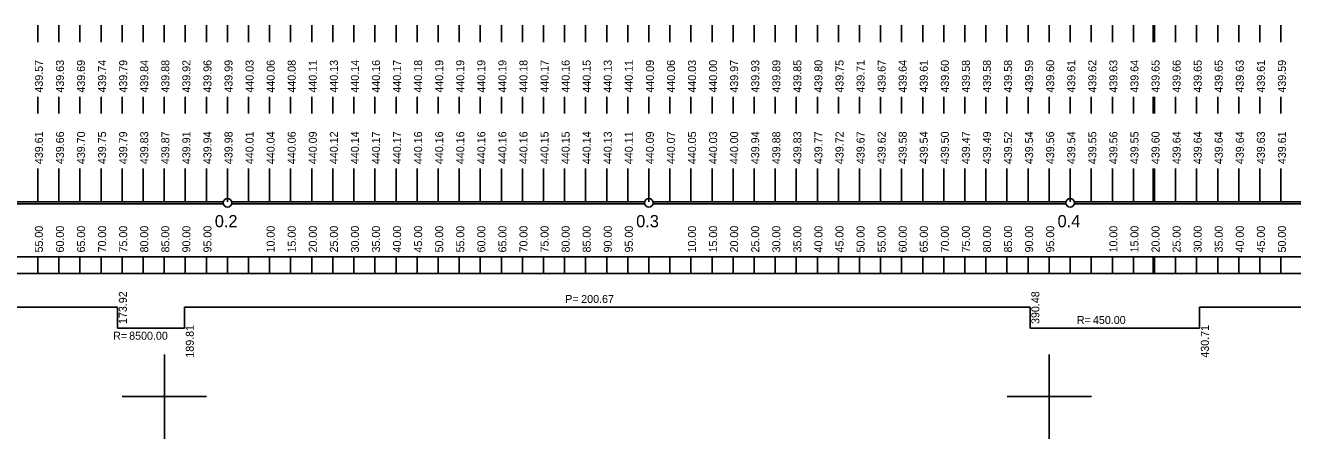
# Model space of a CAD drawing. Extents: x -240 to 1040, y 276 to 593.
# Drawn here: x 157 to 457.8, y 275.7 to 374 of the extents above; entities that cross this region are included whole.
import ezdxf

# ---------------------------------------------------------------- set-up
doc = ezdxf.new("R2010")
doc.units = 0
for name, color, linetype in [('1', 7, 'Continuous'), ('2', 7, 'Continuous'), ('FORMATY', 7, 'Continuous')]:
    doc.layers.add(name, color=color, linetype=linetype)

msp = doc.modelspace()

# ---------------------------------------------------------------- linework, layer by layer
at = {"layer": '1'}
for p, q in [((160, 374), (160, 370)), ((165, 370), (165, 374)), ((170, 374), (170, 370)), ((175, 370), (175, 374)), ((180, 374), (180, 370)), ((185, 370), (185, 374)), ((190, 374), (190, 370)), ((195, 370), (195, 374)), ((200, 374), (200, 370)), ((205, 370), (205, 374)), ((210, 374), (210, 370)), ((215, 370), (215, 374)), ((220, 374), (220, 370)), ((225, 370), (225, 374)), ((230, 374), (230, 370)), ((235, 370), (235, 374)), ((240, 374), (240, 370)), ((245, 370), (245, 374)), ((250, 374), (250, 370)), ((255, 370), (255, 374)), ((260, 374), (260, 370)), ((265, 370), (265, 374)), ((270, 374), (270, 370)), ((275, 370), (275, 374)), ((280, 374), (280, 370)), ((285, 370), (285, 374)), ((290, 374), (290, 370)), ((295, 370), (295, 374)), ((300, 374), (300, 370)), ((305, 370), (305, 374)), ((310, 374), (310, 370)), ((315, 370), (315, 374)), ((320, 374), (320, 370)), ((325, 370), (325, 374)), ((330, 374), (330, 370)), ((335, 370), (335, 374)), ((340, 374), (340, 370)), ((345, 370), (345, 374)), ((350, 374), (350, 370)), ((355, 370), (355, 374)), ((360, 374), (360, 370)), ((365, 370), (365, 374)), ((370, 374), (370, 370)), ((375, 370), (375, 374)), ((380, 374), (380, 370)), ((385, 370), (385, 374)), ((390, 374), (390, 370)), ((395, 370), (395, 374)), ((400, 374), (400, 370)), ((405, 370), (405, 374)), ((410, 374), (410, 370)), ((415, 370), (415, 374)), ((420, 374), (420, 370)), ((424.7, 370), (424.7, 374)), ((425, 374), (425, 370)), ((430, 370), (430, 374)), ((435, 374), (435, 370)), ((440, 370), (440, 374)), ((445, 374), (445, 370)), ((450, 370), (450, 374)), ((455, 374), (455, 370)), ((160, 357), (160, 353)), ((165, 353), (165, 357)), ((170, 357), (170, 353)), ((175, 353), (175, 357)), ((180, 357), (180, 353)), ((185, 353), (185, 357)), ((190, 357), (190, 353)), ((195, 353), (195, 357)), ((200, 357), (200, 353)), ((205, 353), (205, 357)), ((210, 357), (210, 353)), ((215, 353), (215, 357)), ((220, 357), (220, 353)), ((225, 353), (225, 357)), ((230, 357), (230, 353)), ((235, 353), (235, 357)), ((240, 357), (240, 353)), ((245, 353), (245, 357)), ((250, 357), (250, 353)), ((255, 353), (255, 357)), ((260, 357), (260, 353)), ((265, 353), (265, 357)), ((270, 357), (270, 353)), ((275, 353), (275, 357)), ((280, 357), (280, 353)), ((285, 353), (285, 357)), ((290, 357), (290, 353)), ((295, 353), (295, 357)), ((300, 357), (300, 353)), ((305, 353), (305, 357)), ((310, 357), (310, 353)), ((315, 353), (315, 357)), ((320, 357), (320, 353)), ((325, 353), (325, 357)), ((330, 357), (330, 353)), ((335, 353), (335, 357)), ((340, 357), (340, 353)), ((345, 353), (345, 357)), ((350, 357), (350, 353)), ((355, 353), (355, 357)), ((360, 357), (360, 353)), ((365, 353), (365, 357)), ((370, 357), (370, 353)), ((375, 353), (375, 357)), ((380, 357), (380, 353)), ((385, 353), (385, 357)), ((390, 357), (390, 353)), ((395, 353), (395, 357)), ((400, 357), (400, 353)), ((405, 353), (405, 357)), ((410, 357), (410, 353)), ((415, 353), (415, 357)), ((420, 357), (420, 353)), ((424.7, 353), (424.7, 357)), ((425, 357), (425, 353)), ((430, 353), (430, 357)), ((435, 357), (435, 353)), ((440, 353), (440, 357)), ((445, 357), (445, 353)), ((450, 353), (450, 357)), ((455, 357), (455, 353)), ((160, 340), (160, 332)), ((165, 332), (165, 340)), ((170, 340), (170, 332)), ((175, 332), (175, 340)), ((180, 340), (180, 332)), ((185, 332), (185, 340)), ((190, 340), (190, 332)), ((195, 332), (195, 340)), ((200, 340), (200, 332)), ((205, 332), (205, 340)), ((210, 340), (210, 332)), ((215, 332), (215, 340)), ((220, 340), (220, 332)), ((225, 332), (225, 340)), ((230, 340), (230, 332)), ((235, 332), (235, 340)), ((240, 340), (240, 332)), ((245, 332), (245, 340)), ((250, 340), (250, 332)), ((255, 332), (255, 340)), ((260, 340), (260, 332)), ((265, 332), (265, 340)), ((270, 340), (270, 332)), ((275, 332), (275, 340)), ((280, 340), (280, 332)), ((285, 332), (285, 340)), ((290, 340), (290, 332)), ((295, 332), (295, 340)), ((300, 340), (300, 332)), ((305, 332), (305, 340)), ((310, 340), (310, 332)), ((315, 332), (315, 340)), ((320, 340), (320, 332)), ((325, 332), (325, 340)), ((330, 340), (330, 332)), ((335, 332), (335, 340)), ((340, 340), (340, 332)), ((345, 332), (345, 340)), ((350, 340), (350, 332)), ((355, 332), (355, 340)), ((360, 340), (360, 332)), ((365, 332), (365, 340)), ((370, 340), (370, 332)), ((375, 332), (375, 340)), ((380, 340), (380, 332)), ((385, 332), (385, 340)), ((390, 340), (390, 332)), ((395, 332), (395, 340)), ((400, 340), (400, 332)), ((405, 332), (405, 340)), ((410, 340), (410, 332)), ((415, 332), (415, 340)), ((420, 340), (420, 332)), ((424.7, 332), (424.7, 340)), ((425, 340), (425, 332)), ((430, 332), (430, 340)), ((435, 340), (435, 332)), ((440, 332), (440, 340)), ((445, 340), (445, 332)), ((450, 332), (450, 340)), ((455, 340), (455, 332)), ((106, 332), (204, 332)), ((106, 331.6), (204, 331.6)), ((206, 332), (304, 332)), ((206, 331.6), (304, 331.6)), ((306, 332), (404, 332)), ((306, 331.6), (404, 331.6)), ((406, 332), (504, 332)), ((406, 331.6), (504, 331.6)), ((804.78, 319), (5, 319)), ((160, 319), (160, 315)), ((165, 319), (165, 315)), ((170, 319), (170, 315)), ((175, 319), (175, 315)), ((180, 319), (180, 315)), ((185, 319), (185, 315)), ((190, 319), (190, 315)), ((195, 319), (195, 315)), ((200, 319), (200, 315)), ((205, 319), (205, 315)), ((210, 319), (210, 315)), ((215, 319), (215, 315)), ((220, 319), (220, 315)), ((225, 319), (225, 315)), ((230, 319), (230, 315)), ((235, 319), (235, 315)), ((240, 319), (240, 315)), ((245, 319), (245, 315)), ((250, 319), (250, 315)), ((255, 319), (255, 315)), ((260, 319), (260, 315)), ((265, 319), (265, 315)), ((270, 319), (270, 315)), ((275, 319), (275, 315)), ((280, 319), (280, 315)), ((285, 319), (285, 315)), ((290, 319), (290, 315)), ((295, 319), (295, 315)), ((300, 319), (300, 315)), ((305, 319), (305, 315)), ((310, 319), (310, 315)), ((315, 319), (315, 315)), ((320, 319), (320, 315)), ((325, 319), (325, 315)), ((330, 319), (330, 315)), ((335, 319), (335, 315)), ((340, 319), (340, 315)), ((345, 319), (345, 315)), ((350, 319), (350, 315)), ((355, 319), (355, 315)), ((360, 319), (360, 315)), ((365, 319), (365, 315)), ((370, 319), (370, 315)), ((375, 319), (375, 315)), ((380, 319), (380, 315)), ((385, 319), (385, 315)), ((390, 319), (390, 315)), ((395, 319), (395, 315)), ((400, 319), (400, 315)), ((405, 319), (405, 315)), ((410, 319), (410, 315)), ((415, 319), (415, 315)), ((420, 319), (420, 315)), ((424.7, 319), (424.7, 315)), ((425, 319), (425, 315)), ((430, 319), (430, 315)), ((435, 319), (435, 315)), ((440, 319), (440, 315)), ((445, 319), (445, 315)), ((450, 319), (450, 315)), ((455, 319), (455, 315)), ((804.78, 315), (5, 315))]:
    msp.add_line(p, q, dxfattribs=at)
for centre in [(205, 331.8), (305, 331.8), (405, 331.8)]:
    msp.add_circle(centre, 1, dxfattribs=at)
at = {"layer": '2'}
for p, q in [((36.99, 307), (178.92, 307)), ((178.92, 307), (178.92, 302)), ((194.81, 302), (194.81, 307)), ((194.81, 307), (395.48, 307)), ((395.48, 307), (395.48, 302)), ((435.71, 302), (435.71, 307)), ((435.71, 307), (503.92, 307)), ((178.92, 302), (194.81, 302)), ((395.48, 302), (435.71, 302))]:
    msp.add_line(p, q, dxfattribs=at)
at = {"layer": 'FORMATY'}
for p, q in [((190.02, 295.74), (190.02, 275.74)), ((190.02, 295.74), (190.02, 275.74)), ((190.02, 295.74), (190.02, 275.74)), ((190.02, 295.74), (190.02, 275.74)), ((190.02, 295.74), (190.02, 275.74)), ((190.02, 295.74), (190.02, 275.74)), ((190.02, 295.74), (190.02, 275.74)), ((190.02, 295.74), (190.02, 275.74)), ((190.02, 295.74), (190.02, 275.74)), ((400.02, 295.74), (400.02, 275.74)), ((400.02, 295.74), (400.02, 275.74)), ((400.02, 295.74), (400.02, 275.74)), ((400.02, 295.74), (400.02, 275.74)), ((400.02, 295.74), (400.02, 275.74)), ((400.02, 295.74), (400.02, 275.74)), ((400.02, 295.74), (400.02, 275.74)), ((400.02, 295.74), (400.02, 275.74)), ((400.02, 295.74), (400.02, 275.74)), ((180.02, 285.74), (200.02, 285.74)), ((180.02, 285.74), (200.02, 285.74)), ((180.02, 285.74), (200.02, 285.74)), ((180.02, 285.74), (200.02, 285.74)), ((180.02, 285.74), (200.02, 285.74)), ((180.02, 285.74), (200.02, 285.74)), ((180.02, 285.74), (200.02, 285.74)), ((180.02, 285.74), (200.02, 285.74)), ((180.02, 285.74), (200.02, 285.74)), ((390.02, 285.74), (410.02, 285.74)), ((390.02, 285.74), (410.02, 285.74)), ((390.02, 285.74), (410.02, 285.74)), ((390.02, 285.74), (410.02, 285.74)), ((390.02, 285.74), (410.02, 285.74)), ((390.02, 285.74), (410.02, 285.74)), ((390.02, 285.74), (410.02, 285.74)), ((390.02, 285.74), (410.02, 285.74)), ((390.02, 285.74), (410.02, 285.74))]:
    msp.add_line(p, q, dxfattribs=at)

# ---------------------------------------------------------------- texts
at = {"layer": '1'}
for s, p in [('439.61', (161.2, 341)), ('439.66', (166.2, 341)), ('439.70', (171.2, 341)), ('439.75', (176.2, 341)), ('439.79', (181.2, 341)), ('439.83', (186.2, 341)), ('439.87', (191.2, 341)), ('439.91', (196.2, 341)), ('439.94', (201.2, 341)), ('439.98', (206.2, 341)), ('440.01', (211.2, 341)), ('440.04', (216.2, 341)), ('440.06', (221.2, 341)), ('440.09', (226.2, 341)), ('440.12', (231.2, 341)), ('440.14', (236.2, 341)), ('440.17', (241.2, 341)), ('440.17', (246.2, 341)), ('440.16', (251.2, 341)), ('440.16', (256.2, 341)), ('440.16', (261.2, 341)), ('440.16', (266.2, 341)), ('440.16', (271.2, 341)), ('440.16', (276.2, 341)), ('440.15', (281.2, 341)), ('440.15', (286.2, 341)), ('440.14', (291.2, 341)), ('440.13', (296.2, 341)), ('440.11', (301.2, 341)), ('440.09', (306.2, 341)), ('440.07', (311.2, 341)), ('440.05', (316.2, 341)), ('440.03', (321.2, 341)), ('440.00', (326.2, 341)), ('439.94', (331.2, 341)), ('439.88', (336.2, 341)), ('439.83', (341.2, 341)), ('439.77', (346.2, 341)), ('439.72', (351.2, 341)), ('439.67', (356.2, 341)), ('439.62', (361.2, 341)), ('439.58', (366.2, 341)), ('439.54', (371.2, 341)), ('439.50', (376.2, 341)), ('439.47', (381.2, 341)), ('439.49', (386.2, 341)), ('439.52', (391.2, 341)), ('439.54', (396.2, 341)), ('439.56', (401.2, 341)), ('439.54', (406.2, 341)), ('439.55', (411.2, 341)), ('439.56', (416.2, 341)), ('439.55', (421.2, 341)), ('439.60', (426.2, 341)), ('439.64', (431.2, 341)), ('439.64', (436.2, 341)), ('439.64', (441.2, 341)), ('439.64', (446.2, 341)), ('439.63', (451.2, 341)), ('439.61', (456.2, 341)), ('55.00', (161.2, 320)), ('60.00', (166.2, 320)), ('65.00', (171.2, 320)), ('70.00', (176.2, 320)), ('75.00', (181.2, 320)), ('80.00', (186.2, 320)), ('85.00', (191.2, 320)), ('90.00', (196.2, 320)), ('95.00', (201.2, 320)), ('10.00', (216.2, 320)), ('15.00', (221.2, 320)), ('20.00', (226.2, 320)), ('25.00', (231.2, 320)), ('30.00', (236.2, 320)), ('35.00', (241.2, 320)), ('40.00', (246.2, 320)), ('45.00', (251.2, 320)), ('50.00', (256.2, 320)), ('55.00', (261.2, 320)), ('60.00', (266.2, 320)), ('65.00', (271.2, 320)), ('70.00', (276.2, 320)), ('75.00', (281.2, 320)), ('80.00', (286.2, 320)), ('85.00', (291.2, 320)), ('90.00', (296.2, 320)), ('95.00', (301.2, 320)), ('10.00', (316.2, 320)), ('15.00', (321.2, 320)), ('20.00', (326.2, 320)), ('25.00', (331.2, 320)), ('30.00', (336.2, 320)), ('35.00', (341.2, 320)), ('40.00', (346.2, 320)), ('45.00', (351.2, 320)), ('50.00', (356.2, 320)), ('55.00', (361.2, 320)), ('60.00', (366.2, 320)), ('65.00', (371.2, 320)), ('70.00', (376.2, 320)), ('75.00', (381.2, 320)), ('80.00', (386.2, 320)), ('85.00', (391.2, 320)), ('90.00', (396.2, 320)), ('95.00', (401.2, 320)), ('10.00', (416.2, 320)), ('15.00', (421.2, 320)), ('20.00', (426.2, 320)), ('25.00', (431.2, 320)), ('30.00', (436.2, 320)), ('35.00', (441.2, 320)), ('40.00', (446.2, 320)), ('45.00', (451.2, 320)), ('50.00', (456.2, 320))]:
    msp.add_text(s, height=1.9, rotation=90, dxfattribs=at).set_placement(p)
for s, p in [('0.2', (202, 326)), ('0.3', (302, 326)), ('0.4', (402, 326))]:
    msp.add_text(s, height=2.9, dxfattribs=at).set_placement(p)
at = {"layer": '2'}
for s, p in [('439.57', (161.2, 358)), ('439.63', (166.2, 358)), ('439.69', (171.2, 358)), ('439.74', (176.2, 358)), ('439.79', (181.2, 358)), ('439.84', (186.2, 358)), ('439.88', (191.2, 358)), ('439.92', (196.2, 358)), ('439.96', (201.2, 358)), ('439.99', (206.2, 358)), ('440.03', (211.2, 358)), ('440.06', (216.2, 358)), ('440.08', (221.2, 358)), ('440.11', (226.2, 358)), ('440.13', (231.2, 358)), ('440.14', (236.2, 358)), ('440.16', (241.2, 358)), ('440.17', (246.2, 358)), ('440.18', (251.2, 358)), ('440.19', (256.2, 358)), ('440.19', (261.2, 358)), ('440.19', (266.2, 358)), ('440.19', (271.2, 358)), ('440.18', (276.2, 358)), ('440.17', (281.2, 358)), ('440.16', (286.2, 358)), ('440.15', (291.2, 358)), ('440.13', (296.2, 358)), ('440.11', (301.2, 358)), ('440.09', (306.2, 358)), ('440.06', (311.2, 358)), ('440.03', (316.2, 358)), ('440.00', (321.2, 358)), ('439.97', (326.2, 358)), ('439.93', (331.2, 358)), ('439.89', (336.2, 358)), ('439.85', (341.2, 358)), ('439.80', (346.2, 358)), ('439.75', (351.2, 358)), ('439.71', (356.2, 358)), ('439.67', (361.2, 358)), ('439.64', (366.2, 358)), ('439.61', (371.2, 358)), ('439.60', (376.2, 358)), ('439.58', (381.2, 358)), ('439.58', (386.2, 358)), ('439.58', (391.2, 358)), ('439.59', (396.2, 358)), ('439.60', (401.2, 358)), ('439.61', (406.2, 358)), ('439.62', (411.2, 358)), ('439.63', (416.2, 358)), ('439.64', (421.2, 358)), ('439.65', (426.2, 358)), ('439.66', (431.2, 358)), ('439.65', (436.2, 358)), ('439.65', (441.2, 358)), ('439.63', (446.2, 358)), ('439.61', (451.2, 358)), ('439.59', (456.2, 358)), ('173.92', (181.12, 303)), ('390.48', (397.68, 303)), ('189.81', (197.01, 295)), ('430.71', (437.91, 295))]:
    msp.add_text(s, height=1.9, rotation=90, dxfattribs=at).set_placement(p)
for s, p in [('P=', (285.15, 308)), ('200.67', (288.95, 308)), ('R=', (406.59, 303)), ('450.00', (410.39, 303)), ('R=', (177.87, 299.26)), ('8500.00', (181.67, 299.26))]:
    msp.add_text(s, height=1.9, dxfattribs=at).set_placement(p)

doc.saveas('drawing.dxf')
